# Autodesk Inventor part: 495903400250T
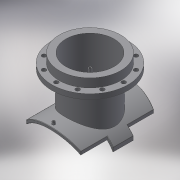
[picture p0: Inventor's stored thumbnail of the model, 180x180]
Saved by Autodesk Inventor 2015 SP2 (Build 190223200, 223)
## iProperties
Created: 2017-10
Part Number: 495903400250T
Material: Generic
Description: PLASSON FLANGED BRANCH SADDLE 315-400X250
Document SubType Name: Modeling
Designer: KIM
Mass: 5602.99 g
Surface Area: 8647.09 cm^2
Volume: 5602.99 cm^3
Density: 1 g/cm^3
Appearance: Default
Author: KIM
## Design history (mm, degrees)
derived "495904.ipt"
feature "Solid1::495904.ipt"
feature "Solid2::495904.ipt"
tag "TaggingFeature1"
body "Solid1"
other parameters: "d1" = 15, "d2" = 283.5, "d4" = 0, "d5" = 315, "d6" = 105, "d7" = 0, "d11" = 2, "d12" = 225.6, "d13" = 14, "d14" = 189, "d16" = 5 deg, "d18" = 4, "d19" = 14, "d20" = 0, "d21" = 3, "d22" = 0, "d36" = 189, "d38" = 0, "d39" = 2, "d40" = 225, "d43" = 395, "d46" = 256, "d47" = 16, "d48" = 10.4, "d49" = 157.5, "d51" = 408, "d53" = 0, "d54" = 22, "d55" = 175, "d57" = 0, "d59" = 360 deg, "d61" = 26, "d63" = 0, "B_" = 315, "H_" = 225, "x_" = 15, "D_" = 16, "D_1" = 395, "t_" = 26, "s_" = 22
